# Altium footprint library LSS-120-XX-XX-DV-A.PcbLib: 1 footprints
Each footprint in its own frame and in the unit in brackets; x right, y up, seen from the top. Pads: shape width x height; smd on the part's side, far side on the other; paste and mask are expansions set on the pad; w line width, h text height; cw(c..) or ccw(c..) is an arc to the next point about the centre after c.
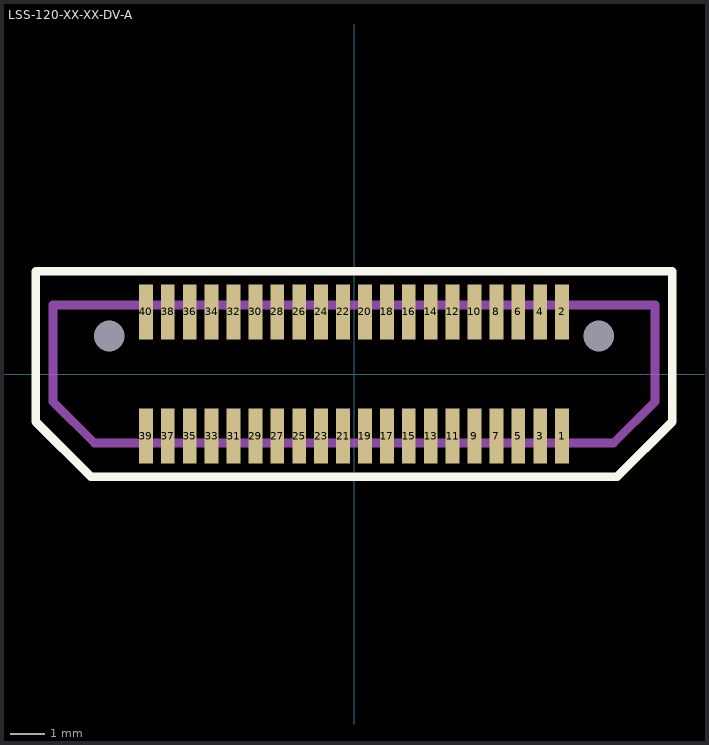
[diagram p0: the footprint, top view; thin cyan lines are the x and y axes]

## LSS-120-XX-XX-DV-A [mm]
pads (42):
  rect 0.4x1.6 smd mask+0.05: 1(6.032,-1.8) 2(6.032,1.8) 3(5.397,-1.8) 4(5.397,1.8) 5(4.763,-1.8) 6(4.763,1.8) 7(4.127,-1.8) 8(4.127,1.8) 9(3.492,-1.8) 10(3.492,1.8) 11(2.857,-1.8) 12(2.857,1.8) 13(2.222,-1.8) 14(2.222,1.8) 15(1.587,-1.8) 16(1.587,1.8) 17(0.953,-1.8) 18(0.953,1.8) 19(0.318,-1.8) 20(0.318,1.8) 21(-0.318,-1.8) 22(-0.318,1.8) 23(-0.953,-1.8) 24(-0.953,1.8) 25(-1.587,-1.8) 26(-1.587,1.8) 27(-2.222,-1.8) 28(-2.222,1.8) 29(-2.857,-1.8) 30(-2.857,1.8) 31(-3.492,-1.8) 32(-3.492,1.8) 33(-4.127,-1.8) 34(-4.127,1.8) 35(-4.763,-1.8) 36(-4.763,1.8) 37(-5.397,-1.8) 38(-5.397,1.8) 39(-6.032,-1.8) 40(-6.032,1.8)
  round 0 hole 0.89 unplated: 41(7.1,1.1) 42(-7.1,1.1)
Top Overlay:
  lines w0.254: -9.225,-1.38 -7.625,-2.98 7.625,-2.98 9.225,-1.38 9.225,2.98 -9.225,2.98 -9.225,-1.38
Mechanical 1:
  lines w0.254: -8.725,-0.8 -7.525,-2 7.525,-2 8.725,-0.8 8.725,2 -8.725,2 -8.725,-0.8
  text "J1" at -0.446,-0.457 h0.76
